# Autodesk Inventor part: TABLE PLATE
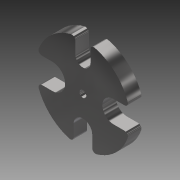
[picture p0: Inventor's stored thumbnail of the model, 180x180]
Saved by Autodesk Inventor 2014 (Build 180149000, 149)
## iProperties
Shininess: 64.0
Length Units: 11272
Angle Units: 11279
Time Units: 11290
Mass Units: 11286
Length Display Precision: 3
Angle Display Precision: 2
Compacted: True
Part Number: TABLE PLATE
Document SubType Name: Modeling
Created: 2003-11
Designer: Autodesk, Inc.
Manufacturer: Standard
Standards Organization: Custom
Mass: 435.491 g
Surface Area: 143.439 cm^2
Volume: 55.5473 cm^3
Density: 7.84 g/cm^3
Material: Steel, High Strength Low Alloy
Appearance: Steel - Polished
Density: 0.0
Volumn: 0.0
Area: 0.0
PropertySet Name: Model Information
Control State: 0
Master: False
Checked Out: False
Author: Autodesk, Inc.
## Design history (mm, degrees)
sketch "Sketch1"
  geometry: C1 r 44.45 at (0, 0); 1 further point
  constraints: 1 centre point, 1 coincident
  dimensions: "d0" = 88.9 diameter of C1
extrude "Extrusion1" new body sketch "Sketch1" distance "d1" = 12.7; taper "d2" = 0 deg
sketch "Sketch2"
  geometry: L1 (-7.137, 43.873)-(-7.137, 28.575); L2 (7.137, 43.873)-(7.137, 28.575); L3 (0, 0)-(0, 40.794); L4 (0, 0)-(-21.298, 0); L5 (-8.725, -28.575)-(-8.725, -43.585); L6 (8.725, -28.575)-(8.725, -43.585); L7 (-28.575, 11.9)-(-42.828, 11.9); L8 (-28.575, -11.9)-(-42.828, -11.9); L9 (28.575, 10.312)-(43.237, 10.312); L10 (28.575, -10.312)-(43.237, -10.312); A1 r 7.137 centre (0, 28.575) between (-7.137, 28.575) and (7.137, 28.575); A2 r 8.725 centre (0, -28.575) between (8.725, -28.575) and (-8.725, -28.575); A3 r 11.9 centre (-28.575, 0) between (-28.575, -11.9) and (-28.575, 11.9); A4 r 10.312 centre (28.575, 0) between (28.575, 10.312) and (28.575, -10.312); A5 r 28.575 centre (0, 0) between (0, 28.575) and (28.575, 0)
  constraints: 20 end point, 11 point on circle, 8 tangent, 5 centre point, 4 horizontal, 4 point on line, 3 parallel, 2 perpendicular, 1 coincident, 1 vertical, 9 other
  dimensions: "d3" = 14.2748 diameter of A1; "d4" = 28.575 distance of L3.start A1.centre; "d7" = 8.7249 radius of A2; "d8" = 28.575 distance of L3.start A2.centre; "d9" = 23.7998 diameter of A3; "d10" = 20.6248 diameter of A4
extrude "Extrusion2" cut sketch "Sketch2" stored distance "d5" = 12.7; taper "d6" = 0 deg
fillet "Fillet1" dims "d11" = 3.175
sketch "Sketch3"
  geometry: C1 r 3.175 at (0, 0); 1 further point
  constraints: 1 centre point, 1 coincident
  dimensions: "d12" = 6.35 diameter of C1
extrude "Extrusion3" cut sketch "Sketch3" stored distance "d13" = 12.7; taper "d14" = 0 deg
body "Solid1"
